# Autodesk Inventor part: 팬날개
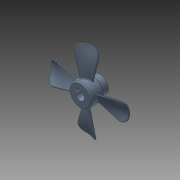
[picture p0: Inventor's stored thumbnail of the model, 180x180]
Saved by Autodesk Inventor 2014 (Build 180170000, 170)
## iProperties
Company: 한국ATC센터
Created: 2016-06
Part Number: 팬날개
Document SubType Name: Modeling
Designer: mdu
Density: 1.06 g/cm^3
Material: ABS 플라스틱
Mass: 29.2868 g
Surface Area: 147.721 cm^2
Volume: 27.6291 cm^3
Appearance: 강청색
Author: mdu
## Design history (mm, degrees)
sketch "스케치1"
  geometry: L1 (-15, 0)-(15, 0); L2 (-15, 0)-(-15, 17); L3 (-15, 17)-(5, 17); L4 (5, 17)-(5, 13); L5 (5, 13)-(15, 13); L6 (15, 13)-(15, 0); 2 further points
  constraints: 12 end point, 3 parallel, 2 perpendicular, 1 coincident, 1 horizontal, 1 midpoint
  dimensions: "d0" = 30 distance of L1.start L1.end; "d8" = 34 diameter of L3 L1; "d10" = 26 diameter of L5 L1; "d32" = 20 distance of L2.end L3.end
revolve "회전1" sketch "스케치1" stored, may be unused: angle "d11" = 90 deg
node "작업 평면2"
sketch "스케치7"
  geometry: L1 (-15, 17)-(5, 17) reference; L2 (-15, -17)-(5, -17) reference; L3 (-5, 17)-(-5, -17); A1 r 35 centre (-36.399, -13.457) between (-2, -7) and (-8, 7); 1 further point
  constraints: 2 end point, 2 midpoint, 2 point on circle, 1 centre point
  dimensions: "d36" = 35 radius of A1; "d37" = 10 distance from line of A1.start L2; "d38" = 10 distance from line of A1.end L1; "d45" = 3 distance from line of A1.end L3; "d46" = 3 distance from line of A1.start L3
sketch "3D 스케치1"
  geometry: L1 through (0, 0) direction (1, 0) reference; L2 through (0, 0) direction (1, 0) reference; 13 other entities
  constraints: 2 collinear
  node "투영 원본 위치 스케치7"
sketch "스케치8"
  geometry: L1 (-15, 17)-(5, 17) reference; L2 (-15, -17)-(5, -17) reference; L3 (-5, 17)-(-5, -17); A1 r 30 centre (-28.74, -3.591) between (-3, -19) and (-9, 19); 1 further point
  constraints: 2 end point, 2 midpoint, 2 point on circle, 1 centre point
  dimensions: "d43" = 30 radius of A1; "d47" = 4 distance from line of A1.end L3; "d48" = 2 distance from line of A1.start L3; "d58" = 2 distance from line of A1.end L1; "d59" = 2 distance from line of A1.start L2
sketch "3D 스케치2"
sketch "3D 스케치3"
feature "경계 패치1" sketch "3D 스케치2", "3D 스케치3" dims "d50" = 0
feature "연장1" dims "d55" = 2
feature "두껍게 하기1" dims "d51" = 2, "d52" = 2
sketch "스케치9"
  geometry: C1 r 59 at (0, 0); 1 further point
  constraints: 1 centre point, 1 coincident
  dimensions: "d60" = 118 diameter of C1
extrude "돌출2" sketch "스케치9" distance "d62" = 200; taper "d63" = 0 deg
fillet "모깎기6" dims "d64" = 10
fillet "모깎기7" dims "d66" = 0.8
fillet "모깎기8" dims "d67" = 0.8
sketch "스케치2"
  geometry: L1 (-2.5, 6)-(-2.5, 8.8); L2 (-2.5, 8.8)-(2.5, 8.8); L3 (2.5, 8.8)-(2.5, 6); A1 r 6.5 centre (0, 0) between (-2.5, 6) and (2.5, 6); 1 further point
  constraints: 6 end point, 2 parallel, 2 point on circle, 1 centre point, 1 coincident, 1 horizontal, 1 vertical
  dimensions: "d12" = 13 diameter of A1; "d13" = 5 distance of L1.end L2.end; "d14" = 15.3 dimension on A1 L2 (computed from d12)
extrude "돌출1" cut sketch "스케치2" stored distance "d15" = 10; taper "d16" = 0 deg
chamfer "모따기1" distance "d17" = 1; stored, may be unused: second distance "d18" = 2, angle "d19" = 45 deg
node "작업 평면1"
fillet "모깎기9" dims "d77" = 2
fillet "모깎기10" dims "d78" = 2
fillet "모깎기11" dims "d79" = 2
node "솔리드1"
pattern_circular "원형 패턴1" dims "d69" = 360 deg
pattern_circular "원형 패턴2" dims angle "d72" = 360 deg
pattern_circular "원형 패턴3" dims angle "d75" = 360 deg
node "투영 원본 위치 스케치8"
node "곡면1"
node "곡면2"
node "곡면3"
node "곡면4"
feature "경계 패치2"
feature "경계 패치3"
feature "경계 패치4"
